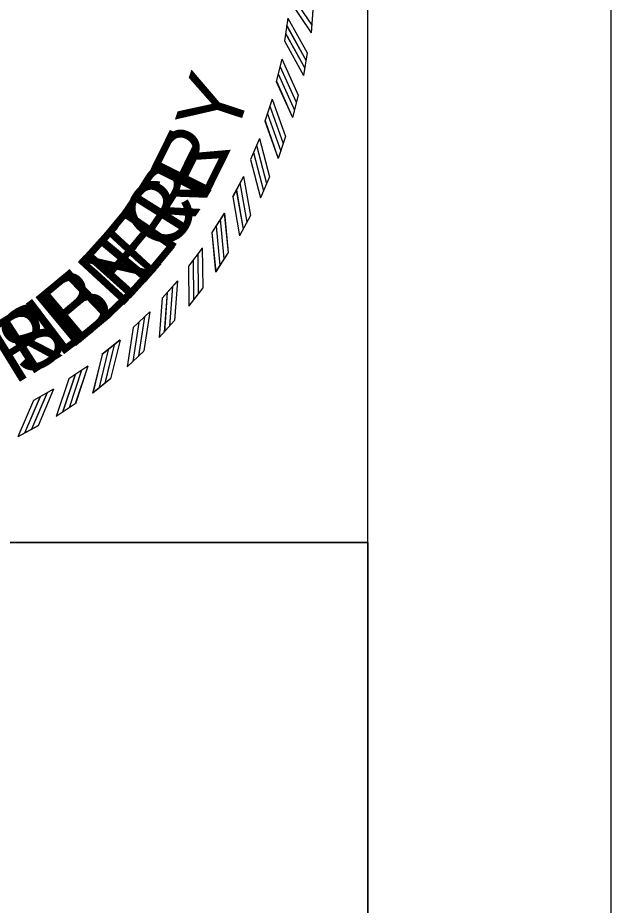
# Model space of a CAD drawing. Extents: x 0 to 1228740, y 0 to 152440.
# Drawn here: x 32.593 to 34, y 16.545 to 18.649 of the extents above; entities that cross this region are included whole.
import ezdxf

# ---------------------------------------------------------------- set-up
doc = ezdxf.new("R2010")
doc.units = 0
for name, color, linetype in [('R_Border', 7, 'Continuous'), ('R_No Plot', 7, 'Continuous'), ('STAMP_Byron', 7, 'Continuous'), ('STAMP_Landon', 7, 'Continuous'), ('STAMP_PP', 7, 'Continuous')]:
    doc.layers.add(name, color=color, linetype=linetype)

msp = doc.modelspace()

# ---------------------------------------------------------------- linework, layer by layer
at = {"layer": 'R_Border'}
msp.add_line((33.4231, 0.5768), (33.4231, 21.4232), dxfattribs=at)
msp.add_lwpolyline([(33.9999, 22), (0, 22), (0, 0), (33.9999, 0)], close=True, dxfattribs=at)
at = {"layer": 'R_No Plot'}
for points in [[(33.4231, 17.4052), (33.4231, 10.8708), (1.516, 10.8708), (1.516, 21.4232), (25.1971, 21.4232), (25.1971, 20.4352), (28.7491, 20.4352), (28.7491, 20.0782), (29.1131, 20.0782), (29.1131, 20.1432), (30.6665, 20.1432)], [(30.6665, 20.1432), (30.6665, 17.4052), (33.4231, 17.4052)]]:
    msp.add_lwpolyline(points, dxfattribs=at)
for points in [[(1.516, 21.4232), (1.516, 0.5768), (33.4231, 0.5768), (33.4231, 17.4052), (30.6665, 17.4052), (30.6665, 20.1432), (29.1131, 20.1432), (29.1131, 20.0782), (28.7491, 20.0782), (28.7491, 20.4352), (25.1971, 20.4352), (25.1971, 21.4232)], [(1.516, 21.4232), (25.1971, 21.4232), (25.1971, 20.4352), (28.7491, 20.4352), (28.7491, 20.0782), (29.1131, 20.0782), (29.1131, 20.1432), (30.6665, 20.1432), (30.6665, 17.4052), (33.4231, 17.4052), (33.4231, 0.5768), (1.516, 0.5768)]]:
    msp.add_lwpolyline(points, close=True, dxfattribs=at)
at = {"layer": 'STAMP_Byron'}
for p, q in [((33.2926, 18.6678), (33.2886, 18.6135)), ((33.2926, 18.6678), (33.2886, 18.6135)), ((33.2337, 18.6484), (33.2252, 18.5945)), ((33.2337, 18.6484), (33.2252, 18.5945)), ((33.2794, 18.566), (33.2709, 18.5123)), ((33.2794, 18.566), (33.2709, 18.5123)), ((33.2191, 18.5516), (33.2062, 18.4986)), ((33.2191, 18.5516), (33.2062, 18.4986)), ((33.1966, 18.4564), (33.1793, 18.4046)), ((33.1966, 18.4564), (33.1793, 18.4046)), ((33.2578, 18.4658), (33.2449, 18.4129)), ((33.2578, 18.4658), (33.2449, 18.4129)), ((33.1662, 18.3633), (33.1448, 18.3132)), ((33.1662, 18.3633), (33.1448, 18.3132)), ((33.228, 18.3676), (33.2108, 18.316)), ((33.228, 18.3676), (33.2108, 18.316)), ((33.1283, 18.2731), (33.1028, 18.2249)), ((33.1283, 18.2731), (33.1028, 18.2249)), ((33.1903, 18.2723), (33.1689, 18.2223)), ((33.1903, 18.2723), (33.1689, 18.2223)), ((33.0831, 18.1863), (33.0537, 18.1404)), ((33.0831, 18.1863), (33.0537, 18.1404)), ((33.1447, 18.1804), (33.1193, 18.1323)), ((33.1447, 18.1804), (33.1193, 18.1323)), ((33.0308, 18.1035), (32.9977, 18.0602)), ((33.0308, 18.1035), (32.9977, 18.0602)), ((33.0918, 18.0925), (33.0625, 18.0467)), ((33.0918, 18.0925), (33.0625, 18.0467)), ((32.9719, 18.0254), (32.9354, 17.9849)), ((32.9719, 18.0254), (32.9354, 17.9849)), ((33.0318, 18.0094), (32.9988, 17.9661)), ((33.0318, 18.0094), (32.9988, 17.9661)), ((32.9068, 17.9523), (32.867, 17.915)), ((32.9068, 17.9523), (32.867, 17.915)), ((32.9651, 17.9315), (32.9286, 17.8911)), ((32.9651, 17.9315), (32.9286, 17.8911)), ((32.8358, 17.8849), (32.7931, 17.851)), ((32.8358, 17.8849), (32.7931, 17.851)), ((32.8922, 17.8593), (32.8525, 17.8221)), ((32.8922, 17.8593), (32.8525, 17.8221)), ((32.7595, 17.8236), (32.7141, 17.7934)), ((32.7595, 17.8236), (32.7141, 17.7934)), ((32.8136, 17.7934), (32.771, 17.7596)), ((32.8136, 17.7934), (32.771, 17.7596)), ((32.6784, 17.7688), (32.6307, 17.7424)), ((32.6784, 17.7688), (32.6307, 17.7424)), ((32.7298, 17.7343), (32.6846, 17.7041)), ((32.7298, 17.7343), (32.6846, 17.7041)), ((32.6415, 17.6822), (32.5939, 17.6559)), ((32.6415, 17.6822), (32.5939, 17.6559))]:
    msp.add_line(p, q, dxfattribs=at)
for points in [[(33.2378, 18.7098), (33.2901, 18.6315)], [(33.2378, 18.7098), (33.2901, 18.6315)], [(33.2363, 18.6917), (33.2886, 18.6134)], [(33.2363, 18.6917), (33.2886, 18.6134)], [(33.2337, 18.6485), (33.2793, 18.5661)], [(33.2337, 18.6485), (33.2793, 18.5661)], [(33.2308, 18.6312), (33.2764, 18.5489)], [(33.2308, 18.6312), (33.2764, 18.5489)], [(33.2283, 18.6125), (33.2739, 18.5301)], [(33.2283, 18.6125), (33.2739, 18.5301)], [(33.2253, 18.5946), (33.2709, 18.5122)], [(33.2253, 18.5946), (33.2709, 18.5122)], [(33.2191, 18.5517), (33.2578, 18.4659)], [(33.2191, 18.5517), (33.2578, 18.4659)], [(33.2107, 18.5163), (33.2494, 18.4304)], [(33.2107, 18.5163), (33.2494, 18.4304)], [(33.2148, 18.5347), (33.2535, 18.4489)], [(33.2148, 18.5347), (33.2535, 18.4489)], [(33.2063, 18.4987), (33.2449, 18.4129)], [(33.2063, 18.4987), (33.2449, 18.4129)], [(33.1965, 18.4564), (33.228, 18.3677)], [(33.1965, 18.4564), (33.228, 18.3677)], [(33.1908, 18.4399), (33.2223, 18.3512)], [(33.1908, 18.4399), (33.2223, 18.3512)], [(33.1853, 18.4218), (33.2167, 18.3331)], [(33.1853, 18.4218), (33.2167, 18.3331)], [(33.1794, 18.4047), (33.2109, 18.316)], [(33.1794, 18.4047), (33.2109, 18.316)], [(33.1592, 18.3474), (33.1832, 18.2563)], [(33.1592, 18.3474), (33.1832, 18.2563)], [(33.1662, 18.3634), (33.1902, 18.2724)], [(33.1662, 18.3634), (33.1902, 18.2724)], [(33.1521, 18.3298), (33.1762, 18.2388)], [(33.1521, 18.3298), (33.1762, 18.2388)], [(33.1448, 18.3132), (33.1689, 18.2222)], [(33.1448, 18.3132), (33.1689, 18.2222)], [(33.1283, 18.2732), (33.1447, 18.1805)], [(33.1283, 18.2732), (33.1447, 18.1805)], [(33.12, 18.2578), (33.1364, 18.1651)], [(33.12, 18.2578), (33.1364, 18.1651)], [(33.1029, 18.2249), (33.1193, 18.1322)], [(33.1029, 18.2249), (33.1193, 18.1322)], [(33.1115, 18.2409), (33.1279, 18.1482)], [(33.1115, 18.2409), (33.1279, 18.1482)], [(33.0831, 18.1864), (33.0918, 18.0926)], [(33.0831, 18.1864), (33.0918, 18.0926)], [(33.0735, 18.1717), (33.0822, 18.078)], [(33.0735, 18.1717), (33.0822, 18.078)], [(33.0537, 18.1404), (33.0625, 18.0467)], [(33.0537, 18.1404), (33.0625, 18.0467)], [(33.0637, 18.1556), (33.0724, 18.0618)], [(33.0637, 18.1556), (33.0724, 18.0618)], [(33.0308, 18.1036), (33.0318, 18.0095)], [(33.0308, 18.1036), (33.0318, 18.0095)], [(33.0089, 18.0745), (33.0099, 17.9804)], [(33.0089, 18.0745), (33.0099, 17.9804)], [(33.0201, 18.0898), (33.021, 17.9957)], [(33.0201, 18.0898), (33.021, 17.9957)], [(32.9978, 18.0602), (32.9988, 17.9661)], [(32.9978, 18.0602), (32.9988, 17.9661)], [(32.9601, 18.0126), (32.9533, 17.9187)], [(32.9601, 18.0126), (32.9533, 17.9187)], [(32.9719, 18.0254), (32.9651, 17.9315)], [(32.9719, 18.0254), (32.9651, 17.9315)], [(32.9477, 17.9983), (32.9409, 17.9044)], [(32.9477, 17.9983), (32.9409, 17.9044)], [(32.9354, 17.9849), (32.9286, 17.891)], [(32.9354, 17.9849), (32.9286, 17.891)], [(32.9068, 17.9524), (32.8922, 17.8594)], [(32.9068, 17.9524), (32.8922, 17.8594)], [(32.8804, 17.9273), (32.8658, 17.8343)], [(32.8804, 17.9273), (32.8658, 17.8343)], [(32.8939, 17.9405), (32.8793, 17.8475)], [(32.8939, 17.9405), (32.8793, 17.8475)], [(32.8671, 17.915), (32.8525, 17.822)], [(32.8671, 17.915), (32.8525, 17.822)], [(32.8358, 17.885), (32.8136, 17.7935)], [(32.8358, 17.885), (32.8136, 17.7935)], [(32.822, 17.8742), (32.7998, 17.7828)], [(32.822, 17.8742), (32.7998, 17.7828)], [(32.7931, 17.851), (32.771, 17.7595)], [(32.7931, 17.851), (32.771, 17.7595)], [(32.8075, 17.8622), (32.7853, 17.7707)], [(32.8075, 17.8622), (32.7853, 17.7707)], [(32.7595, 17.8237), (32.7299, 17.7343)], [(32.7595, 17.8237), (32.7299, 17.7343)], [(32.7294, 17.8033), (32.6997, 17.7139)], [(32.7294, 17.8033), (32.6997, 17.7139)], [(32.7449, 17.8141), (32.7152, 17.7248)], [(32.7449, 17.8141), (32.7152, 17.7248)], [(32.7142, 17.7934), (32.6845, 17.704)], [(32.7142, 17.7934), (32.6845, 17.704)], [(32.663, 17.7605), (32.6261, 17.674)], [(32.663, 17.7605), (32.6261, 17.674)], [(32.6784, 17.7689), (32.6415, 17.6823)], [(32.6784, 17.7689), (32.6415, 17.6823)], [(32.6308, 17.7424), (32.5938, 17.6558)], [(32.6308, 17.7424), (32.5938, 17.6558)], [(32.6467, 17.751), (32.6098, 17.6644)], [(32.6467, 17.751), (32.6098, 17.6644)]]:
    msp.add_lwpolyline(points, dxfattribs=at)
at = {"layer": 'STAMP_Landon'}
for p, q in [((33.2925, 18.6678), (33.2886, 18.6135)), ((33.2337, 18.6484), (33.2252, 18.5945)), ((33.2793, 18.5661), (33.2709, 18.5123)), ((33.2191, 18.5516), (33.2062, 18.4986)), ((33.1965, 18.4564), (33.1793, 18.4046)), ((33.2578, 18.4658), (33.2449, 18.4129)), ((33.1662, 18.3633), (33.1448, 18.3132)), ((33.228, 18.3677), (33.2108, 18.316)), ((33.1283, 18.2731), (33.1028, 18.2249)), ((33.1902, 18.2723), (33.1689, 18.2223)), ((33.0831, 18.1863), (33.0537, 18.1404)), ((33.1447, 18.1804), (33.1193, 18.1323)), ((33.0308, 18.1035), (32.9977, 18.0602)), ((33.0918, 18.0926), (33.0625, 18.0467)), ((32.9719, 18.0254), (32.9354, 17.9849)), ((33.0318, 18.0094), (32.9988, 17.9662)), ((32.9068, 17.9523), (32.867, 17.915)), ((32.9651, 17.9315), (32.9286, 17.8911)), ((32.8358, 17.8849), (32.7931, 17.8511)), ((32.8922, 17.8593), (32.8525, 17.8221)), ((32.7595, 17.8236), (32.7141, 17.7934)), ((32.8136, 17.7934), (32.771, 17.7596)), ((32.6784, 17.7688), (32.6307, 17.7424)), ((32.7298, 17.7343), (32.6846, 17.7041)), ((32.6415, 17.6822), (32.5939, 17.6559))]:
    msp.add_line(p, q, dxfattribs=at)
for points in [[(33.2378, 18.7098), (33.2901, 18.6315)], [(33.2363, 18.6917), (33.2886, 18.6135)], [(33.2337, 18.6485), (33.2793, 18.5661)], [(33.2308, 18.6312), (33.2764, 18.5489)], [(33.2282, 18.6125), (33.2739, 18.5301)], [(33.2253, 18.5946), (33.2709, 18.5123)], [(33.2191, 18.5517), (33.2578, 18.4659)], [(33.2107, 18.5163), (33.2494, 18.4304)], [(33.2148, 18.5347), (33.2535, 18.4489)], [(33.2062, 18.4987), (33.2449, 18.4129)], [(33.1965, 18.4565), (33.228, 18.3677)], [(33.1908, 18.4399), (33.2223, 18.3512)], [(33.1853, 18.4218), (33.2167, 18.3331)], [(33.1794, 18.4047), (33.2108, 18.316)], [(33.1592, 18.3474), (33.1832, 18.2564)], [(33.1662, 18.3634), (33.1902, 18.2724)], [(33.1521, 18.3298), (33.1762, 18.2388)], [(33.1448, 18.3132), (33.1689, 18.2222)], [(33.1283, 18.2732), (33.1447, 18.1805)], [(33.12, 18.2578), (33.1364, 18.1651)], [(33.1029, 18.2249), (33.1193, 18.1322)], [(33.1115, 18.2409), (33.1279, 18.1482)], [(33.0831, 18.1864), (33.0918, 18.0927)], [(33.0735, 18.1717), (33.0822, 18.078)], [(33.0537, 18.1404), (33.0625, 18.0467)], [(33.0636, 18.1556), (33.0724, 18.0619)], [(33.0308, 18.1036), (33.0318, 18.0095)], [(33.0089, 18.0745), (33.0099, 17.9804)], [(33.0201, 18.0898), (33.021, 17.9957)], [(32.9978, 18.0602), (32.9988, 17.9661)], [(32.9601, 18.0126), (32.9532, 17.9187)], [(32.9719, 18.0255), (32.9651, 17.9316)], [(32.9477, 17.9983), (32.9409, 17.9044)], [(32.9354, 17.9849), (32.9286, 17.891)], [(32.9068, 17.9524), (32.8922, 17.8594)], [(32.8804, 17.9273), (32.8658, 17.8343)], [(32.8939, 17.9406), (32.8793, 17.8476)], [(32.8671, 17.9151), (32.8525, 17.8221)], [(32.8358, 17.885), (32.8136, 17.7935)], [(32.822, 17.8743), (32.7998, 17.7828)], [(32.7931, 17.8511), (32.771, 17.7596)], [(32.8074, 17.8622), (32.7853, 17.7707)], [(32.7595, 17.8237), (32.7299, 17.7344)], [(32.7294, 17.8033), (32.6997, 17.714)], [(32.7449, 17.8141), (32.7152, 17.7248)], [(32.7142, 17.7934), (32.6845, 17.704)], [(32.663, 17.7606), (32.6261, 17.674)], [(32.6784, 17.7689), (32.6415, 17.6823)], [(32.6308, 17.7424), (32.5938, 17.6558)], [(32.6467, 17.7511), (32.6098, 17.6645)]]:
    msp.add_lwpolyline(points, dxfattribs=at)
at = {"layer": 'STAMP_PP'}
for p, q in [((33.2925, 18.6677), (33.2885, 18.6135)), ((33.2337, 18.6484), (33.2252, 18.5945)), ((33.2793, 18.566), (33.2708, 18.5123)), ((33.2191, 18.5516), (33.2062, 18.4986)), ((33.1965, 18.4563), (33.1793, 18.4046)), ((33.2577, 18.4657), (33.2449, 18.4129)), ((33.1662, 18.3633), (33.1447, 18.3131)), ((33.228, 18.3676), (33.2108, 18.316)), ((33.1283, 18.273), (33.1027, 18.2248)), ((33.1902, 18.2722), (33.1688, 18.2222)), ((33.083, 18.1863), (33.0536, 18.1403)), ((33.1447, 18.1803), (33.1192, 18.1323)), ((33.0308, 18.1035), (32.9977, 18.0601)), ((33.0917, 18.0925), (33.0624, 18.0467)), ((32.9719, 18.0253), (32.9353, 17.9849)), ((33.0317, 18.0093), (32.9987, 17.9661)), ((32.9067, 17.9523), (32.8669, 17.915)), ((32.965, 17.9314), (32.9286, 17.8911)), ((32.8357, 17.8849), (32.793, 17.851)), ((32.8922, 17.8593), (32.8525, 17.8221)), ((32.7595, 17.8236), (32.7141, 17.7933)), ((32.8136, 17.7934), (32.7709, 17.7596)), ((32.6784, 17.7688), (32.6306, 17.7424)), ((32.7298, 17.7342), (32.6845, 17.704)), ((32.6414, 17.6822), (32.5938, 17.6558))]:
    msp.add_line(p, q, dxfattribs=at)
for points in [[(33.2378, 18.7098), (33.29, 18.6315)], [(33.2363, 18.6917), (33.2885, 18.6134)], [(33.2336, 18.6484), (33.2793, 18.5661)], [(33.2307, 18.6312), (33.2764, 18.5488)], [(33.2282, 18.6124), (33.2739, 18.5301)], [(33.2252, 18.5945), (33.2709, 18.5122)], [(33.219, 18.5517), (33.2577, 18.4658)], [(33.2107, 18.5162), (33.2493, 18.4304)], [(33.2147, 18.5347), (33.2534, 18.4489)], [(33.2062, 18.4986), (33.2449, 18.4128)], [(33.1965, 18.4564), (33.228, 18.3677)], [(33.1908, 18.4398), (33.2223, 18.3511)], [(33.1852, 18.4218), (33.2167, 18.3331)], [(33.1793, 18.4046), (33.2108, 18.3159)], [(33.1591, 18.3473), (33.1832, 18.2563)], [(33.1662, 18.3634), (33.1902, 18.2723)], [(33.1521, 18.3298), (33.1761, 18.2388)], [(33.1448, 18.3132), (33.1688, 18.2222)], [(33.1282, 18.2731), (33.1447, 18.1804)], [(33.1199, 18.2577), (33.1364, 18.165)], [(33.1028, 18.2249), (33.1193, 18.1322)], [(33.1114, 18.2408), (33.1279, 18.1481)], [(33.083, 18.1863), (33.0917, 18.0926)], [(33.0734, 18.1717), (33.0822, 18.0779)], [(33.0537, 18.1404), (33.0624, 18.0466)], [(33.0636, 18.1555), (33.0723, 18.0618)], [(33.0308, 18.1036), (33.0317, 18.0094)], [(33.0089, 18.0745), (33.0098, 17.9803)], [(33.02, 18.0898), (33.021, 17.9956)], [(32.9977, 18.0602), (32.9987, 17.966)], [(32.96, 18.0125), (32.9532, 17.9186)], [(32.9719, 18.0254), (32.9651, 17.9315)], [(32.9477, 17.9982), (32.9408, 17.9043)], [(32.9354, 17.9849), (32.9286, 17.891)], [(32.9067, 17.9524), (32.8922, 17.8594)], [(32.8803, 17.9273), (32.8658, 17.8343)], [(32.8938, 17.9405), (32.8793, 17.8475)], [(32.867, 17.915), (32.8525, 17.822)], [(32.8358, 17.885), (32.8136, 17.7935)], [(32.8219, 17.8742), (32.7998, 17.7827)], [(32.7931, 17.851), (32.7709, 17.7595)], [(32.8074, 17.8621), (32.7852, 17.7706)], [(32.7595, 17.8237), (32.7298, 17.7343)], [(32.7293, 17.8032), (32.6997, 17.7139)], [(32.7448, 17.8141), (32.7152, 17.7247)], [(32.7142, 17.7933), (32.6845, 17.704)], [(32.663, 17.7605), (32.6261, 17.6739)], [(32.6784, 17.7688), (32.6415, 17.6823)], [(32.6307, 17.7424), (32.5938, 17.6558)], [(32.6467, 17.751), (32.6097, 17.6644)]]:
    msp.add_lwpolyline(points, dxfattribs=at)

# ---------------------------------------------------------------- texts
at = {"layer": 'STAMP_Byron'}
for s, rotation, p in [('E', 63.7362, (33.0351, 18.2082)), ('E', 63.7362, (33.0351, 18.2082)), ('C', 56.0754, (32.9507, 18.0835)), ('C', 56.0754, (32.9507, 18.0835)), ('N', 47.3202, (32.8349, 17.9563)), ('N', 47.3202, (32.8349, 17.9563)), ('E', 39.6594, (32.7187, 17.8605)), ('E', 39.6594, (32.7187, 17.8605)), ('R', 31.6338, (32.5844, 17.7778)), ('R', 31.6338, (32.5844, 17.7778))]:
    msp.add_text(s, height=0.1503, rotation=rotation, dxfattribs=at).set_placement(p)
at = {"layer": 'STAMP_Landon'}
for s, rotation, p in [('R', 57.9868, (32.9809, 18.1257)), ('E', 50.326, (32.886, 18.009)), ('L', 43.7596, (32.7928, 17.9198)), ('L', 37.1932, (32.6901, 17.8418)), ('I', 32.8156, (32.6169, 17.7966))]:
    msp.add_text(s, height=0.1503, rotation=rotation, dxfattribs=at).set_placement(p)
at = {"layer": 'STAMP_PP'}
for s, rotation, p in [('Y', 71.7733, (33.1072, 18.3567)), ('R', 63.7477, (33.0384, 18.2148)), ('R', 55.7221, (32.9504, 18.084)), ('E', 48.0613, (32.8502, 17.9717)), ('B', 40.0357, (32.7301, 17.8695)), ('S', 32.7397, (32.6095, 17.7919))]:
    msp.add_text(s, height=0.1503, rotation=rotation, dxfattribs=at).set_placement(p)

doc.saveas('drawing.dxf')
